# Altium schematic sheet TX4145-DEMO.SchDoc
size A
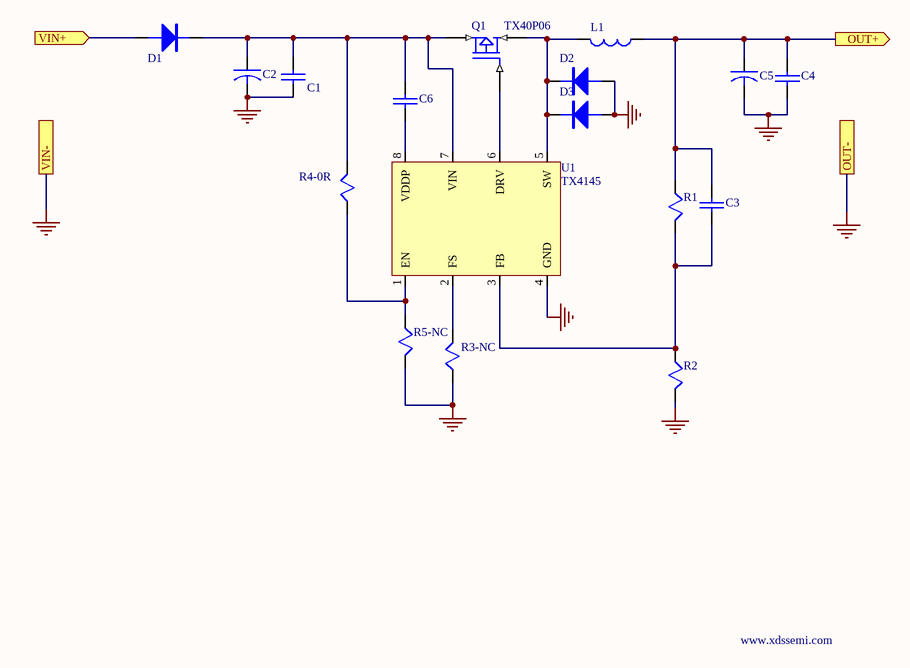
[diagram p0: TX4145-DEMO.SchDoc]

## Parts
C1  CAP  [0805R]  (value not drawn)
C2  (no value)  [c8*12]
C3  (no value)  [0805R]
C4  (no value)  [1206R]
C5  (no value)  [C8*12]
C6  (no value)  [0805R]
D1  DIODE  [SMB]  (value not drawn)
D2  (no value)  [SMB]
D3  (no value)  [SMB]
L1  (no value)  [CDRH127]
Q1  TX40P06
R1  (no value)  [0805R]
R2  (no value)  [0805R]
R3-NC  (no value)  [0805R]
R4-0R  (no value)  [0805R]
R5-NC  (no value)  [0805R]
U1  TX4145  [SOIC8]

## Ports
OUT+ (out), OUT-, VIN+ (in), VIN-

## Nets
GND: C1.2 C2.2 C4.2 C5.2 D2.1(A) D3.1(A) R2.2 R3-NC.1 R5-NC.2 U1.4(GND) ; port VIN-, port OUT-
OUT+: C3.1 C4.1 C5.1 L1.1 R1.1 ; port OUT+
VIN+: D1.1(A) ; port VIN+
NetC1_1: C1.1 C2.1 C6.2 D1.2(K) Q1.2(D) R4-0R.2 U1.7(VIN)
NetC3_2: C3.2 R1.2 R2.1 U1.3(FB)
NetC6_1: C6.1 U1.8(VDDP)
NetD2_2: D2.2(K) D3.2(K) L1.2 Q1.3(S) U1.5(SW)
NetQ1_1: Q1.1(G) U1.6(DRV)
NetR3-NC_2: R3-NC.2 U1.2(FS)
NetR4-0R_1: R4-0R.1 R5-NC.1 U1.1(EN)

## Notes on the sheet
- www.xdssemi.com

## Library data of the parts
C1 C3 C4 C6 = CAP: Capacitor
C2 C5 = CAPACITOR
D2 D3 = DIODE
L1 = INDUCTOR
Q1 = MOSFET P
R1 R2 R3-NC R4-0R R5-NC = RES1_1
